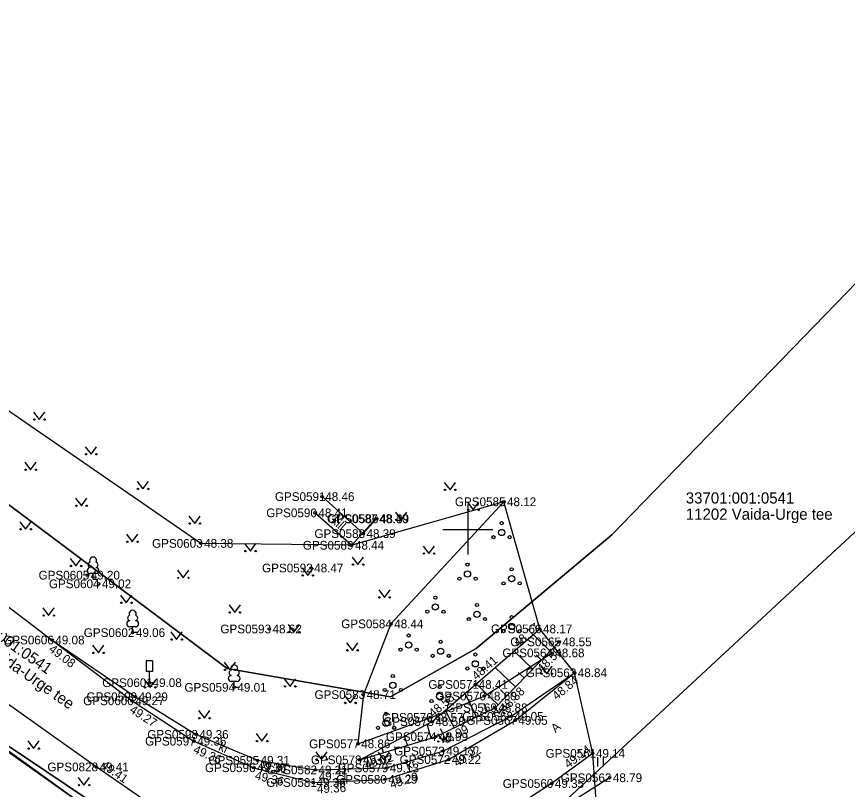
# Model space of a CAD drawing. Extents: x 551623 to 559850, y 6561220 to 6567135.
# Drawn here: x 555313.8 to 555380.4, y 6565529.1 to 6565591.2 of the extents above; entities that cross this region are included whole.
import ezdxf

# ---------------------------------------------------------------- set-up
doc = ezdxf.new("R2010")
doc.units = 0
for name, color, linetype in [('AED', 7, 'Continuous'), ('HALJASTUS', 7, 'Continuous'), ('KORGUS-EH2000', 7, 'Continuous'), ('LIIKLUS', 7, 'Continuous'), ('MOOTKORG-EH2000', 7, 'Continuous'), ('MOOTMPUNKT', 7, 'Continuous'), ('MOOTNR', 7, 'Continuous'), ('MOOTPIIR', 7, 'Continuous'), ('PIIR', 7, 'Continuous'), ('PUU', 7, 'Continuous'), ('RELJEEF', 7, 'Continuous'), ('TEE', 7, 'Continuous'), ('VORK', 7, 'Continuous')]:
    doc.layers.add(name, color=color, linetype=linetype)

msp = doc.modelspace()

# ---------------------------------------------------------------- linework, layer by layer
at = {"layer": 'AED'}
for points in [[(555338.308, 6565552.639), (555341.616, 6565549.668), (555342.688, 6565550.852)], [(555324.003, 6565524.39), (555318.054, 6565528.671), (555308.195, 6565535.788)]]:
    msp.add_lwpolyline(points, dxfattribs=at)
at = {"layer": 'HALJASTUS'}
for p, q in [((555315.169, 6565559.421), (555315.632, 6565558.815)), ((555315.632, 6565558.815), (555316.078, 6565559.421)), ((555319.324, 6565556.639), (555319.787, 6565556.033)), ((555319.787, 6565556.033), (555320.233, 6565556.639)), ((555314.47, 6565555.397), (555314.933, 6565554.79)), ((555314.933, 6565554.79), (555315.379, 6565555.397)), ((555323.478, 6565553.857), (555323.942, 6565553.251)), ((555323.942, 6565553.251), (555324.387, 6565553.857)), ((555348.11, 6565553.777), (555348.574, 6565553.171)), ((555348.574, 6565553.171), (555349.019, 6565553.777)), ((555318.55, 6565552.507), (555319.013, 6565551.9)), ((555319.013, 6565551.9), (555319.459, 6565552.507)), ((555349.972, 6565552.18), (555350.435, 6565551.573)), ((555350.435, 6565551.573), (555350.88, 6565552.18)), ((555344.196, 6565551.39), (555344.659, 6565550.784)), ((555344.659, 6565550.784), (555345.105, 6565551.39)), ((555327.633, 6565551.076), (555328.096, 6565550.469)), ((555328.096, 6565550.469), (555328.542, 6565551.076)), ((555314.068, 6565550.626), (555314.532, 6565550.019)), ((555314.532, 6565550.019), (555314.977, 6565550.626)), ((555322.63, 6565549.616), (555323.093, 6565549.01)), ((555323.093, 6565549.01), (555323.539, 6565549.616)), ((555332.103, 6565548.876), (555332.566, 6565548.269)), ((555332.566, 6565548.269), (555333.012, 6565548.876)), ((555346.412, 6565548.668), (555346.876, 6565548.062)), ((555346.876, 6565548.062), (555347.321, 6565548.668)), ((555318.105, 6565547.676), (555318.569, 6565547.069)), ((555318.569, 6565547.069), (555319.014, 6565547.676)), ((555340.729, 6565547.788), (555341.192, 6565547.181)), ((555341.192, 6565547.181), (555341.638, 6565547.788)), ((555326.71, 6565546.726), (555327.173, 6565546.119)), ((555327.173, 6565546.119), (555327.619, 6565546.726)), ((555336.704, 6565546.919), (555337.167, 6565546.313)), ((555337.167, 6565546.313), (555337.613, 6565546.919)), ((555322.142, 6565544.726), (555322.606, 6565544.119)), ((555322.606, 6565544.119), (555323.051, 6565544.726)), ((555342.853, 6565545.157), (555343.317, 6565544.55)), ((555343.317, 6565544.55), (555343.762, 6565545.157)), ((555315.911, 6565543.704), (555316.374, 6565543.097)), ((555316.374, 6565543.097), (555316.82, 6565543.704)), ((555330.85, 6565543.956), (555331.314, 6565543.349)), ((555331.314, 6565543.349), (555331.759, 6565543.956)), ((555335.591, 6565542.368), (555336.055, 6565541.761)), ((555336.055, 6565541.761), (555336.5, 6565542.368)), ((555326.179, 6565541.776), (555326.643, 6565541.169)), ((555326.643, 6565541.169), (555327.088, 6565541.776)), ((555319.911, 6565540.703), (555320.374, 6565540.096)), ((555320.374, 6565540.096), (555320.82, 6565540.703)), ((555340.282, 6565540.908), (555340.745, 6565540.301)), ((555340.745, 6565540.301), (555341.19, 6565540.908)), ((555330.464, 6565539.339), (555330.928, 6565538.732)), ((555330.928, 6565538.732), (555331.373, 6565539.339)), ((555355.864, 6565539.033), (555356.328, 6565538.427)), ((555356.328, 6565538.427), (555356.773, 6565539.033)), ((555335.285, 6565538.01), (555335.748, 6565537.404)), ((555335.748, 6565537.404), (555336.193, 6565538.01)), ((555324.061, 6565537.932), (555324.524, 6565537.325)), ((555324.524, 6565537.325), (555324.97, 6565537.932)), ((555340.105, 6565536.682), (555340.568, 6565536.075)), ((555340.568, 6565536.075), (555341.014, 6565536.682)), ((555328.408, 6565535.463), (555328.872, 6565534.856)), ((555328.872, 6565534.856), (555329.317, 6565535.463)), ((555352.04, 6565535.835), (555352.503, 6565535.228)), ((555352.503, 6565535.228), (555352.948, 6565535.835)), ((555333.031, 6565533.629), (555333.494, 6565533.023)), ((555333.494, 6565533.023), (555333.94, 6565533.629)), ((555347.57, 6565533.593), (555348.034, 6565532.986)), ((555348.034, 6565532.986), (555348.479, 6565533.593)), ((555314.711, 6565533.027), (555315.174, 6565532.421)), ((555315.174, 6565532.421), (555315.62, 6565533.027)), ((555337.808, 6565532.154), (555338.272, 6565531.548)), ((555338.272, 6565531.548), (555338.717, 6565532.154)), ((555342.804, 6565532.127), (555343.268, 6565531.52)), ((555343.268, 6565531.52), (555343.713, 6565532.127)), ((555360.408, 6565531.728), (555360.408, 6565530.967)), ((555360.863, 6565531.728), (555360.863, 6565530.967)), ((555318.755, 6565530.087), (555319.218, 6565529.48)), ((555319.218, 6565529.48), (555319.663, 6565530.087))]:
    msp.add_line(p, q, dxfattribs=at)
for points in [[(555352.887, 6565552.222), (555343.839, 6565542.424), (555341.626, 6565536.746), (555341.19, 6565532.798), (555347.045, 6565534.922), (555351.318, 6565536.631), (555356.762, 6565540.094)], [(555361.377, 6565530.075), (555353.295, 6565524.933), (555351.719, 6565521.845), (555350.973, 6565518.729), (555353.476, 6565515.91)]]:
    msp.add_lwpolyline(points, dxfattribs=at)
for centre in [(555315.231, 6565558.815), (555316.06, 6565558.815), (555319.386, 6565556.033), (555320.215, 6565556.033), (555314.532, 6565554.79), (555315.361, 6565554.79), (555323.541, 6565553.251), (555324.37, 6565553.251), (555348.173, 6565553.171), (555349.001, 6565553.171), (555318.612, 6565551.9), (555319.441, 6565551.9), (555350.034, 6565551.573), (555350.863, 6565551.573), (555344.258, 6565550.784), (555345.087, 6565550.784), (555314.131, 6565550.019), (555314.96, 6565550.019), (555327.695, 6565550.469), (555328.524, 6565550.469), (555322.692, 6565549.01), (555323.521, 6565549.01), (555332.165, 6565548.269), (555332.994, 6565548.269), (555346.475, 6565548.062), (555347.303, 6565548.062), (555318.168, 6565547.069), (555318.997, 6565547.069), (555340.791, 6565547.181), (555341.62, 6565547.181), (555326.772, 6565546.119), (555327.601, 6565546.119), (555336.766, 6565546.313), (555337.595, 6565546.313), (555322.205, 6565544.119), (555323.034, 6565544.119), (555342.916, 6565544.55), (555343.744, 6565544.55), (555330.913, 6565543.349), (555331.742, 6565543.349), (555315.973, 6565543.097), (555316.802, 6565543.097), (555335.654, 6565541.761), (555336.483, 6565541.761), (555326.242, 6565541.169), (555327.071, 6565541.169), (555319.973, 6565540.096), (555320.802, 6565540.096), (555340.344, 6565540.301), (555341.173, 6565540.301), (555330.527, 6565538.732), (555331.355, 6565538.732), (555355.926, 6565538.427), (555356.755, 6565538.427), (555324.123, 6565537.325), (555324.952, 6565537.325), (555335.347, 6565537.404), (555336.176, 6565537.404), (555340.167, 6565536.075), (555340.996, 6565536.075), (555328.471, 6565534.856), (555329.3, 6565534.856), (555352.102, 6565535.228), (555352.931, 6565535.228), (555333.093, 6565533.023), (555333.922, 6565533.023), (555347.633, 6565532.986), (555348.461, 6565532.986), (555314.773, 6565532.421), (555315.602, 6565532.421), (555337.871, 6565531.548), (555338.7, 6565531.548), (555342.867, 6565531.52), (555343.695, 6565531.52), (555318.817, 6565529.48), (555319.646, 6565529.48)]:
    msp.add_circle(centre, 0.055, dxfattribs=at)
at = {"layer": 'KORGUS-EH2000'}
for centre in [(555352.887, 6565552.222), (555328.595, 6565548.883), (555340.689, 6565548.734), (555337.42, 6565546.908), (555320.395, 6565545.64), (555334.079, 6565542.015), (555343.839, 6565542.424), (555355.774, 6565542.022), (555316.66, 6565541.129), (555357.329, 6565540.98), (555358.561, 6565538.499), (555350.613, 6565537.562), (555341.626, 6565536.746), (555323.074, 6565536.252), (555352.191, 6565535.69), (555347.141, 6565534.581), (555347.421, 6565533.37), (555328.036, 6565533.009), (555360.017, 6565532.032), (555333.123, 6565531.478), (555341.337, 6565531.511), (555348.456, 6565531.532), (555320.204, 6565530.941), (555332.837, 6565530.879), (555337.764, 6565530.704), (555343.363, 6565529.946), (555361.377, 6565530.075), (555337.611, 6565529.695)]:
    msp.add_circle(centre, 0.1, dxfattribs=at)
at = {"layer": 'LIIKLUS'}
for p, q in [((555324.208, 6565539.453), (555324.208, 6565538.603)), ((555324.708, 6565539.453), (555324.208, 6565539.453)), ((555324.708, 6565539.453), (555324.708, 6565538.603)), ((555324.708, 6565538.603), (555324.208, 6565538.603)), ((555324.458, 6565538.603), (555324.458, 6565537.703)), ((555324.708, 6565537.703), (555324.458, 6565537.703))]:
    msp.add_line(p, q, dxfattribs=at)
at = {"layer": 'MOOTMPUNKT'}
for centre in [(555338.308, 6565552.639), (555352.887, 6565552.222), (555337.756, 6565551.335), (555342.634, 6565550.874), (555342.688, 6565550.852), (555341.616, 6565549.668), (555328.595, 6565548.883), (555340.689, 6565548.734), (555337.42, 6565546.908), (555319.496, 6565546.333), (555320.395, 6565545.64), (555334.079, 6565542.015), (555343.839, 6565542.424), (555355.774, 6565542.022), (555323.122, 6565541.722), (555316.66, 6565541.129), (555357.329, 6565540.98), (555356.762, 6565540.094), (555358.561, 6565538.499), (555324.458, 6565537.703), (555331.263, 6565537.329), (555350.613, 6565537.562), (555323.338, 6565536.578), (555341.626, 6565536.746), (555351.318, 6565536.631), (555323.074, 6565536.252), (555352.191, 6565535.69), (555347.045, 6565534.922), (555347.141, 6565534.581), (555353.479, 6565535.005), (555353.801, 6565534.677), (555328.214, 6565533.554), (555347.421, 6565533.37), (555328.036, 6565533.009), (555341.19, 6565532.798), (555348.011, 6565532.218), (555360.017, 6565532.032), (555333.123, 6565531.478), (555341.337, 6565531.511), (555348.456, 6565531.532), (555320.204, 6565530.941), (555332.837, 6565530.879), (555337.764, 6565530.704), (555343.481, 6565530.862), (555343.363, 6565529.946), (555361.377, 6565530.075), (555337.611, 6565529.695), (555356.722, 6565529.611)]:
    msp.add_circle(centre, 0.1, dxfattribs=at)
at = {"layer": 'MOOTPIIR'}
for points in [[(555361.463, 6565511.386), (555360.017, 6565532.032), (555358.561, 6565538.499), (555355.774, 6565542.022), (555352.887, 6565552.222), (555340.689, 6565548.734), (555328.595, 6565548.883), (555311.005, 6565561)], [(555308.145, 6565535.689), (555318.054, 6565528.671), (555330.348, 6565519.912), (555338.917, 6565513.849), (555343.606, 6565507.989), (555343.396, 6565504.481), (555344.278, 6565498.871), (555347.549, 6565485.98), (555349.833, 6565472.665), (555351.862, 6565468.498), (555351.364, 6565466.022), (555364.788, 6565450.448), (555366.463, 6565449.495), (555372.25, 6565447.625), (555390.067, 6565444.356), (555415.239, 6565438.401), (555428.65, 6565435.15), (555427.952, 6565432.688), (555420.104, 6565396.88), (555415.382, 6565376.075), (555413.205, 6565364.686), (555411.398, 6565356.944)]]:
    msp.add_lwpolyline(points, dxfattribs=at)
at = {"layer": 'PIIR'}
for points in [[(555160.12, 6565598.86), (555193.24, 6565604.68), (555193.7, 6565602.7), (555225.47, 6565605.89), (555234.35, 6565605.6), (555251.24, 6565598.48), (555330.71, 6565538.85), (555343.81, 6565536.56), (555350.68, 6565540.44), (555361.56, 6565549.57), (555419.65, 6565609.54), (555428.83, 6565620.98), (555435.71, 6565632.72), (555438.85, 6565638.78), (555447.07, 6565659.22), (555507.46, 6565826.66)], [(555524.79, 6565820.16), (555464.46, 6565652.92), (555447.97, 6565611.96), (555353.12, 6565523.87), (555343.14, 6565512.46), (555302.6, 6565539.71), (555242.37, 6565583.94), (555179.42, 6565586.32), (555138.98, 6565580.6), (555121.18, 6565602.26), (555116.17, 6565610.5), (555109.96, 6565624.83), (555093.56, 6565628.47), (555079.04, 6565618.4), (555074.13, 6565607.82), (555075.34, 6565593.24), (555091.74, 6565551.94), (555171.91, 6565394.64), (555191.35, 6565341.19)], [(555435.71, 6565632.72), (555428.83, 6565620.98), (555419.65, 6565609.54), (555361.56, 6565549.57), (555350.68, 6565540.44), (555343.81, 6565536.56), (555330.71, 6565538.85), (555251.24, 6565598.48), (555234.35, 6565605.6), (555223.17, 6565668.21)]]:
    msp.add_lwpolyline(points, dxfattribs=at)
for points in [[(555353.12, 6565523.87), (555447.97, 6565611.96), (555496.51, 6565604.38), (555470.4, 6565439.4), (555419.74, 6565450.66), (555368.05, 6565461.11), (555358.8, 6565482.45)], [(555153.01, 6565448.47), (555161.15, 6565451.45), (555173.66, 6565456.03), (555207.29, 6565506.14), (555287.77, 6565518.56), (555302.6, 6565539.71), (555343.14, 6565512.46), (555319.44, 6565481.04), (555323.07, 6565461.26), (555312.9, 6565433.84), (555316.84, 6565372.52), (555318.72, 6565342.57), (555320.51, 6565314.61), (555303.13, 6565302.54), (555208.78, 6565303.3), (555205.15, 6565297.11), (555200.72, 6565310.3), (555206.9, 6565339.44), (555221.23, 6565376.06), (555216.83, 6565392.35), (555207.22, 6565406.57)]]:
    msp.add_lwpolyline(points, close=True, dxfattribs=at)
at = {"layer": 'PUU'}
for p, q in [((555320.186, 6565546.461), (555319.705, 6565546.461)), ((555319.945, 6565545.986), (555319.945, 6565546.461)), ((555320.326, 6565545.986), (555319.945, 6565545.986)), ((555323.362, 6565542.197), (555322.882, 6565542.197)), ((555323.122, 6565541.722), (555323.122, 6565542.197)), ((555323.502, 6565541.722), (555323.122, 6565541.722)), ((555331.503, 6565537.804), (555331.023, 6565537.804)), ((555331.263, 6565537.329), (555331.263, 6565537.804)), ((555331.643, 6565537.329), (555331.263, 6565537.329))]:
    msp.add_line(p, q, dxfattribs=at)
for centre, radius in [((555352.713, 6565550.509), 0.125), ((555352.713, 6565549.759), 0.25), ((555352.063, 6565549.384), 0.125), ((555353.363, 6565549.384), 0.125), ((555349.974, 6565547.179), 0.125), ((555349.974, 6565546.429), 0.25), ((555353.513, 6565546.799), 0.125), ((555349.324, 6565546.054), 0.125), ((555350.624, 6565546.054), 0.125), ((555353.513, 6565546.049), 0.25), ((555352.863, 6565545.674), 0.125), ((555354.163, 6565545.674), 0.125), ((555347.404, 6565544.522), 0.125), ((555347.404, 6565543.772), 0.25), ((555350.732, 6565543.932), 0.125), ((555346.754, 6565543.397), 0.125), ((555348.054, 6565543.397), 0.125), ((555350.732, 6565543.182), 0.25), ((555350.082, 6565542.807), 0.125), ((555351.382, 6565542.807), 0.125), ((555353.513, 6565542.963), 0.125), ((555353.513, 6565542.213), 0.25), ((555345.255, 6565541.487), 0.125), ((555352.863, 6565541.838), 0.125), ((555354.163, 6565541.838), 0.125), ((555345.255, 6565540.737), 0.25), ((555347.825, 6565540.981), 0.125), ((555344.605, 6565540.362), 0.125), ((555345.905, 6565540.362), 0.125), ((555347.175, 6565539.856), 0.125), ((555347.825, 6565540.231), 0.25), ((555348.475, 6565539.856), 0.125), ((555350.606, 6565539.969), 0.125), ((555350.606, 6565539.219), 0.25), ((555349.956, 6565538.844), 0.125), ((555351.256, 6565538.844), 0.125), ((555343.991, 6565538.241), 0.125), ((555343.991, 6565537.491), 0.25), ((555347.741, 6565537.355), 0.125), ((555343.341, 6565537.116), 0.125), ((555344.641, 6565537.116), 0.125), ((555347.741, 6565536.605), 0.25), ((555347.091, 6565536.23), 0.125), ((555348.391, 6565536.23), 0.125), ((555343.443, 6565535.205), 0.125), ((555343.443, 6565534.455), 0.25), ((555342.793, 6565534.08), 0.125), ((555344.093, 6565534.08), 0.125)]:
    msp.add_circle(centre, radius, dxfattribs=at)
for centre, radius, start, end in [((555319.775, 6565547.159), 0.233, 109.02174, 253.14154), ((555319.945, 6565547.506), 0.277, 332.5799, 207.4201), ((555320.116, 6565547.159), 0.233, 286.85082, 70.98591), ((555319.708, 6565546.699), 0.238, 90.0016, 269.3953), ((555320.183, 6565546.699), 0.238, 270.6047, 89.9984), ((555323.122, 6565543.242), 0.277, 332.5799, 207.4201), ((555322.885, 6565542.434), 0.238, 90.0016, 269.3953), ((555322.952, 6565542.894), 0.233, 109.02174, 253.14154), ((555323.292, 6565542.894), 0.233, 286.85082, 70.98591), ((555323.359, 6565542.434), 0.238, 270.6047, 89.9984), ((555331.093, 6565538.501), 0.233, 109.02174, 253.14154), ((555331.263, 6565538.849), 0.277, 332.5799, 207.4201), ((555331.433, 6565538.501), 0.233, 286.85082, 70.98591), ((555331.026, 6565538.041), 0.238, 90.0016, 269.3953), ((555331.501, 6565538.041), 0.238, 270.6047, 89.9984)]:
    msp.add_arc(centre, radius, start, end, dxfattribs=at)
at = {"layer": 'RELJEEF'}
for p, q in [((555356.604, 6565540.233), (555355.239, 6565541.559)), ((555355.211, 6565538.799), (555353.72, 6565540.247)), ((555355.907, 6565539.516), (555355.479, 6565539.932)), ((555353.817, 6565537.364), (555352.201, 6565538.934)), ((555354.514, 6565538.082), (555354.048, 6565538.534)), ((555352.424, 6565535.93), (555350.682, 6565537.622)), ((555350.693, 6565534.961), (555349.777, 6565536.844)), ((555353.12, 6565536.647), (555352.617, 6565537.136)), ((555351.592, 6565535.399), (555351.283, 6565536.034)), ((555348.894, 6565534.087), (555348.208, 6565535.497)), ((555349.793, 6565534.524), (555349.553, 6565535.018)), ((555347.075, 6565533.264), (555346.738, 6565534.368)), ((555347.995, 6565533.649), (555347.823, 6565534.002)), ((555345.162, 6565532.68), (555344.937, 6565533.416)), ((555346.119, 6565532.972), (555346.034, 6565533.248)), ((555343.25, 6565532.095), (555343.137, 6565532.463)), ((555344.206, 6565532.388), (555344.155, 6565532.553)), ((555342.293, 6565531.803), (555342.276, 6565531.858))]:
    msp.add_line(p, q, dxfattribs=at)
for points in [[(555341.337, 6565531.511), (555347.141, 6565534.581), (555350.613, 6565537.562), (555355.774, 6565542.022)], [(555341.337, 6565531.511), (555347.421, 6565533.37), (555352.191, 6565535.69), (555357.329, 6565540.98)]]:
    msp.add_lwpolyline(points, dxfattribs=at)
at = {"layer": 'TEE'}
for points in [[(555272.683, 6565590.134), (555271.484, 6565588.076), (555270.516, 6565586.416), (555269.723, 6565584.609), (555268.981, 6565582.24), (555268.55, 6565578.954), (555269.504, 6565576.952), (555281.044, 6565568.103), (555297.768, 6565555.508), (555316.66, 6565541.129), (555323.074, 6565536.252), (555328.036, 6565533.009), (555332.837, 6565530.879), (555337.611, 6565529.695), (555343.363, 6565529.946), (555348.456, 6565531.532), (555353.801, 6565534.677), (555358.561, 6565538.499)], [(555337.756, 6565551.335), (555340.689, 6565548.734), (555342.634, 6565550.874)], [(555316.66, 6565541.129), (555323.338, 6565536.578), (555328.214, 6565533.554), (555333.123, 6565531.478), (555337.764, 6565530.704), (555343.481, 6565530.862), (555348.011, 6565532.218), (555353.479, 6565535.005), (555358.561, 6565538.499)], [(555324.447, 6565527.997), (555320.204, 6565530.941), (555310.534, 6565537.807)], [(555360.017, 6565532.032), (555356.722, 6565529.611), (555352.039, 6565526.571)]]:
    msp.add_lwpolyline(points, dxfattribs=at)
at = {"layer": 'VORK'}
for p, q in [((555350, 6565552), (555350, 6565548)), ((555348, 6565550), (555352, 6565550))]:
    msp.add_line(p, q, dxfattribs=at)

# ---------------------------------------------------------------- texts
at = {"layer": 'KORGUS-EH2000'}
for s, p in [(' 48.12', (555352.887, 6565551.872)), (' 48.38', (555328.595, 6565548.533)), (' 48.44', (555340.689, 6565548.384)), (' 48.47', (555337.42, 6565546.558)), (' 49.02', (555320.395, 6565545.29)), (' 48.44', (555343.839, 6565542.074)), (' 48.62', (555334.079, 6565541.665)), (' 48.71', (555341.626, 6565536.396)), (' 48.79', (555361.377, 6565529.725))]:
    msp.add_text(s, height=0.7, dxfattribs=at).set_placement(p)
for s, rotation, p in [(' 48.17', 40.82907, (555353.856, 6565540.319)), (' 49.08', 322.748, (555316.13, 6565540.433)), (' 48.55', 45.83229, (555355.794, 6565538.281)), (' 48.41', 40.82907, (555350.499, 6565537.695)), (' 48.84', 38.75949, (555356.917, 6565536.115)), (' 48.88', 45.83229, (555352.818, 6565535.08)), (' 48.58', 40.64841, (555347.027, 6565534.714)), (' 49.27', 326.83219, (555322.595, 6565535.519)), (' 48.99', 25.93657, (555347.803, 6565532.583)), (' 49.14', 36.30544, (555357.849, 6565530.649)), (' 49.36', 336.08226, (555327.681, 6565532.209)), (' 49.02', 16.99075, (555341.592, 6565530.674)), (' 49.22', 30.47829, (555348.9, 6565530.778)), (' 49.41', 325.24801, (555320.303, 6565531.085)), (' 49.31', 350.52947, (555332.911, 6565530.811)), (' 49.36', 346.0646, (555332.626, 6565530.03)), (' 49.21', 1.58012, (555337.789, 6565529.829)), (' 49.29', 17.2918, (555343.624, 6565529.111)), (' 49.36', 2.5046, (555337.65, 6565528.821))]:
    msp.add_text(s, height=0.7, rotation=rotation, dxfattribs=at).set_placement(p)
at = {"layer": 'MOOTKORG-EH2000'}
for s, p in [(' 48.46', (555338.308, 6565552.289)), (' 48.12', (555352.887, 6565551.872)), (' 48.41', (555337.756, 6565550.985)), (' 48.40', (555342.634, 6565550.524)), (' 48.39', (555342.688, 6565550.502)), (' 48.39', (555341.616, 6565549.318)), (' 48.38', (555328.595, 6565548.533)), (' 48.44', (555340.689, 6565548.384)), (' 49.20', (555319.496, 6565545.983)), (' 48.47', (555337.42, 6565546.558)), (' 49.02', (555320.395, 6565545.29)), (' 48.44', (555343.839, 6565542.074)), (' 49.06', (555323.122, 6565541.372)), (' 48.62', (555334.079, 6565541.665)), (' 48.17', (555355.774, 6565541.672)), (' 49.08', (555316.66, 6565540.779)), (' 48.55', (555357.329, 6565540.63)), (' 48.68', (555356.762, 6565539.744)), (' 48.84', (555358.561, 6565538.149)), (' 49.08', (555324.458, 6565537.353)), (' 49.01', (555331.263, 6565536.979)), (' 48.41', (555350.613, 6565537.212)), (' 49.29', (555323.338, 6565536.228)), (' 48.71', (555341.626, 6565536.396)), (' 48.60', (555351.318, 6565536.281)), (' 49.27', (555323.074, 6565535.901)), (' 48.88', (555352.191, 6565535.34)), (' 49.05', (555353.479, 6565534.655)), (' 48.57', (555347.045, 6565534.572)), (' 48.58', (555347.141, 6565534.231)), (' 49.05', (555353.801, 6565534.327)), (' 49.36', (555328.036, 6565532.659)), (' 49.36', (555328.214, 6565533.204)), (' 48.99', (555347.421, 6565533.02)), (' 48.86', (555341.19, 6565532.447)), (' 49.13', (555348.011, 6565531.868)), (' 49.14', (555360.017, 6565531.682)), (' 49.31', (555333.123, 6565531.128)), (' 49.02', (555341.337, 6565531.161)), (' 49.22', (555348.456, 6565531.182)), (' 49.41', (555320.204, 6565530.591)), (' 49.36', (555332.837, 6565530.529)), (' 49.21', (555337.764, 6565530.354)), (' 49.13', (555343.481, 6565530.512)), (' 49.36', (555337.611, 6565529.345)), (' 49.29', (555343.363, 6565529.596)), (' 48.79', (555361.377, 6565529.725)), (' 49.35', (555356.722, 6565529.262))]:
    msp.add_text(s, height=0.7, dxfattribs=at).set_placement(p)
at = {"layer": 'MOOTNR'}
for s, p in [('GPS0591 ', (555334.528, 6565552.289)), ('GPS0585 ', (555348.967, 6565551.872)), ('GPS0590 ', (555333.837, 6565550.985)), ('GPS0587 ', (555338.714, 6565550.524)), ('GPS0586 ', (555338.768, 6565550.502)), ('GPS0588 ', (555337.697, 6565549.318)), ('GPS0603 ', (555324.676, 6565548.533)), ('GPS0589 ', (555336.77, 6565548.384)), ('GPS0605 ', (555315.577, 6565545.983)), ('GPS0592 ', (555333.501, 6565546.558)), ('GPS0604 ', (555316.405, 6565545.29)), ('GPS0584 ', (555339.85, 6565542.074)), ('GPS0602 ', (555319.202, 6565541.372)), ('GPS0593 ', (555330.159, 6565541.665)), ('GPS0566 ', (555351.855, 6565541.672)), ('GPS0606 ', (555312.74, 6565540.779)), ('GPS0565 ', (555353.409, 6565540.63)), ('GPS0564 ', (555352.772, 6565539.744)), ('GPS0563 ', (555354.641, 6565538.149)), ('GPS0601 ', (555320.679, 6565537.353)), ('GPS0594 ', (555327.273, 6565536.979)), ('GPS0571 ', (555346.833, 6565537.212)), ('GPS0599 ', (555319.419, 6565536.228)), ('GPS0583 ', (555337.706, 6565536.396)), ('GPS0570 ', (555347.398, 6565536.281)), ('GPS0600 ', (555319.154, 6565535.901)), ('GPS0569 ', (555348.271, 6565535.34)), ('GPS0568 ', (555349.56, 6565534.655)), ('GPS0576 ', (555343.125, 6565534.572)), ('GPS0575 ', (555343.221, 6565534.231)), ('GPS0567 ', (555349.881, 6565534.327)), ('GPS0597 ', (555324.116, 6565532.659)), ('GPS0598 ', (555324.294, 6565533.204)), ('GPS0574 ', (555343.431, 6565533.02)), ('GPS0577 ', (555337.27, 6565532.447)), ('GPS0573 ', (555344.092, 6565531.868)), ('GPS0561 ', (555356.238, 6565531.682)), ('GPS0595 ', (555329.203, 6565531.128)), ('GPS0578 ', (555337.417, 6565531.161)), ('GPS0572 ', (555344.536, 6565531.182)), ('GPS0828 ', (555316.284, 6565530.591)), ('GPS0596 ', (555328.917, 6565530.529)), ('GPS0582 ', (555333.845, 6565530.354)), ('GPS0579 ', (555339.561, 6565530.512)), ('GPS0581 ', (555333.832, 6565529.345)), ('GPS0580 ', (555339.444, 6565529.596)), ('GPS0562 ', (555357.457, 6565529.725)), ('GPS0560 ', (555352.803, 6565529.262))]:
    msp.add_text(s, height=0.7, dxfattribs=at).set_placement(p)
at = {"layer": 'PIIR'}
for s, p in [('33701:001:0541', (555367.484, 6565552.081)), ('11202 Vaida-Urge tee', (555367.484, 6565550.781))]:
    msp.add_text(s, height=0.9, dxfattribs=at).set_placement(p)
for s, p in [('33701:001:0541', (555309.122, 6565543.318)), ('11202 Vaida-Urge tee', (555308.38, 6565542.251))]:
    msp.add_text(s, height=0.9, rotation=325.15344, dxfattribs=at).set_placement(p)
at = {"layer": 'TEE'}
for s, rotation, p in [('kill', 318.38637, (555339.003, 6565550.604)), ('A', 40.03993, (555357.028, 6565533.654)), ('kr', 336.03664, (555329.944, 6565532.309)), ('kr', 17.24617, (555345.156, 6565530.715))]:
    msp.add_text(s, height=0.7, rotation=rotation, dxfattribs=at).set_placement(p)

doc.saveas('drawing.dxf')
